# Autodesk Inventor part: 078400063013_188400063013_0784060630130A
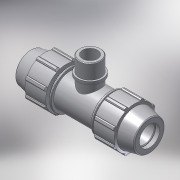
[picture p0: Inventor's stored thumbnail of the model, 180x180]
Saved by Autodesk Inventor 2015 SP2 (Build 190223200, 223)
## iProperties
Created: 2017-02
Part Number: 078400063013_188400063013_0784060630130A
Material: PVC-Piping
Description: PLASSON TEE WITH THREADED MALE OFFTAKE 63-1.1/4"-63
Document SubType Name: Modeling
Designer: KIM
Mass: 92.6774 g
Surface Area: 199.44 cm^2
Volume: 66.1981 cm^3
Density: 1.4 g/cm^3
Appearance: Smooth - White
Author: Кирилл
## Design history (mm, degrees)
derived "07840.ipt"
feature "Solid1::07840.ipt"
feature "Solid2::07840.ipt"
tag "TaggingFeature1"
body "Solid1"
body "Solid2"
other parameters: "d2" = 63, "d4" = 11.16667, "d5" = 32.16, "d7" = 113, "d11" = 4.46667, "d13" = 120 deg, "d14" = 94.5, "d15" = 12 deg, "d16" = 98.31, "d18" = 3.15, "d19" = 35 deg, "d20" = 17.5 deg, "d21" = 105.09, "d23" = 0, "d25" = 360 deg, "d27" = 2.26, "d33" = 1.26, "d42" = 48.24, "d43" = 3.39, "d46" = 1.89, "d68" = 4.46667, "d72" = 79, "d73" = 41.91, "d74" = 22, "d75" = 48.1965, "d76" = 29.337, "d77" = 26.4, "d80" = 1.2573, "d91" = 84.75, "d93" = 113, "d95" = 56.7, "d99" = 268, "d101" = 0, "d103" = 0, "d105" = 0, "d_" = 63, "E_" = 113, "A_" = 79, "l_" = 113, "l_2" = 22, "H_" = 268, "R_" = 41.91
